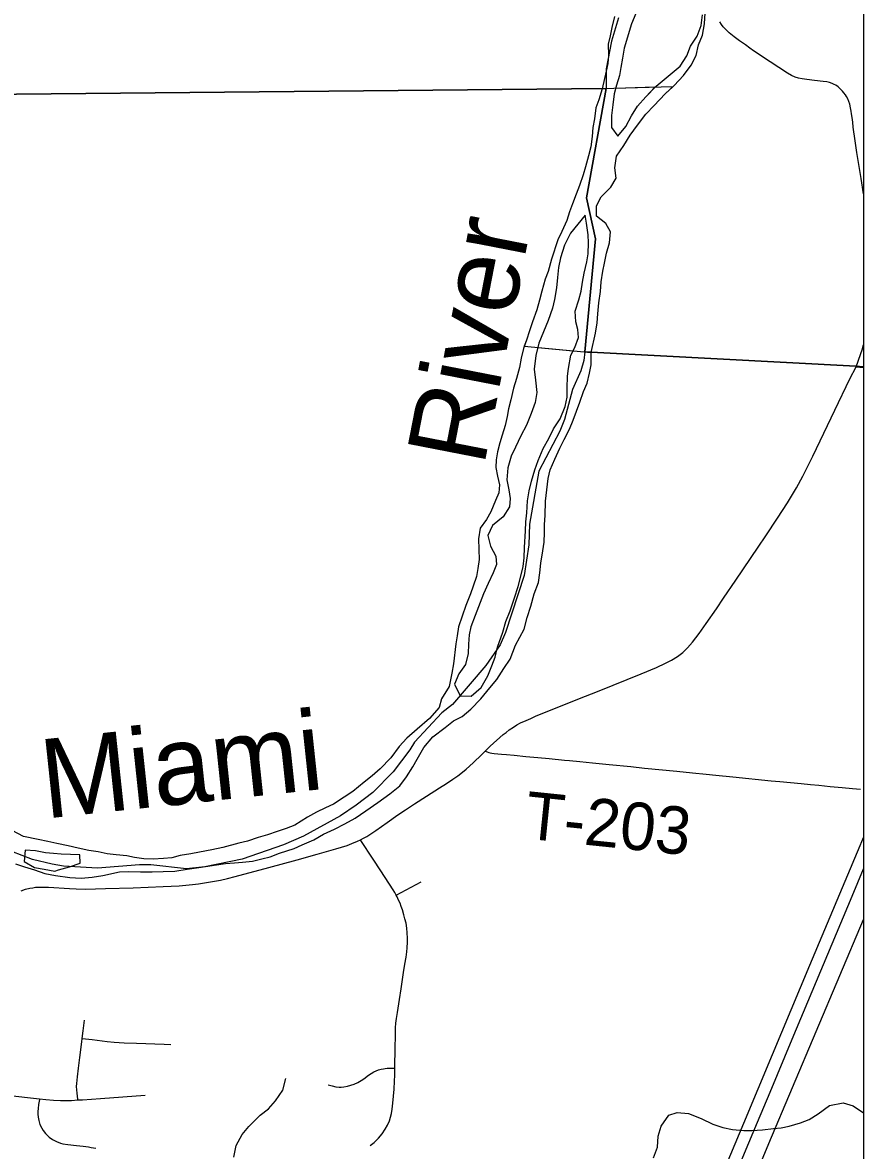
# Model space of a CAD drawing. Extents: x -87 to 2145, y -2128 to 440.
# Drawn here: x 255.22 to 281.8, y 178.57 to 214.23 of the extents above; entities that cross this region are included whole.
import ezdxf

# ---------------------------------------------------------------- set-up
doc = ezdxf.new("R2010")
doc.units = 0
for name, color, linetype in [('GM_X_County_Road', 7, 'Continuous'), ('GM_X_Interstate_Route', 7, 'Continuous'), ('GM_X_Major_River', 7, 'Continuous'), ('GM_X_Major_River_Text', 7, 'Continuous'), ('GM_X_Minor_River', 7, 'Continuous'), ('GM_X_Rail_Line', 7, 'Continuous'), ('GM_X_Township', 7, 'Continuous'), ('GM_X_Township_Road', 7, 'Continuous'), ('GM_X_Township_Road_Text', 7, 'Continuous'), ('GM_X_Township_Text', 7, 'Continuous'), ('SH_Cut_Line', 7, 'Continuous'), ('SH_Text', 7, 'Continuous')]:
    doc.layers.add(name, color=color, linetype=linetype)

msp = doc.modelspace()

# ---------------------------------------------------------------- linework, layer by layer
at = {"layer": 'GM_X_County_Road'}
msp.add_line((281.567, 203.349), (281.801, 203.326), dxfattribs=at)
at = {"layer": 'GM_X_Interstate_Route'}
for points in [[(278.018, 179.429), (278.929, 181.6), (280.107, 184.432), (281.696, 188.213), (281.801, 188.464)], [(278.453, 179.463), (278.849, 180.409), (279.553, 182.088), (281.44, 186.615), (281.801, 187.473)], [(265.644, 155.016), (265.806, 155.447), (265.948, 155.792), (266.105, 156.136), (266.281, 156.489), (266.476, 156.851), (266.665, 157.178), (267.768, 158.911), (268.709, 160.389), (270.982, 163.9), (271.858, 165.306), (272.07, 165.657), (272.693, 166.735), (273.419, 168.076), (274.226, 169.653), (274.883, 171.028), (275.672, 172.831), (276.978, 175.947), (278.453, 179.463)], [(268.918, 161.401), (269.569, 162.413), (270.91, 164.496), (271.65, 165.698), (272.583, 167.319), (273.388, 168.824), (274.151, 170.369), (274.821, 171.832), (275.854, 174.245), (277.608, 178.454), (278.018, 179.429)]]:
    msp.add_lwpolyline(points, dxfattribs=at)
at = {"layer": 'GM_X_Major_River'}
for p, q in [((275.773, 212.196), (273.543, 212.136)), ((275.21, 212.181), (273.967, 212.148)), ((271.077, 203.996), (273.198, 203.799)), ((271.507, 203.956), (272.621, 203.853))]:
    msp.add_line(p, q, dxfattribs=at)
for points in [[(273.198, 203.799), (273.327, 204.406), (273.389, 204.735), (273.409, 205.025), (273.441, 205.365), (273.494, 205.725), (273.515, 206.035), (273.567, 206.365), (273.616, 206.624), (273.678, 206.933), (273.769, 207.262), (273.802, 207.612), (273.661, 207.878), (273.358, 208.109), (273.359, 208.431), (273.51, 208.717), (273.812, 209.028), (273.983, 209.313), (273.944, 209.636), (273.997, 210.005), (274.23, 210.339), (274.432, 210.673), (274.654, 210.987), (274.917, 211.33), (275.188, 211.611), (275.532, 211.971), (275.822, 212.242), (276.114, 212.554), (276.357, 212.877), (276.508, 213.183), (276.59, 213.521), (276.711, 213.829), (276.774, 214.188), (276.797, 214.539)], [(273.933, 214.418), (273.85, 214.069), (273.791, 213.81), (273.731, 213.541), (273.739, 213.189), (273.72, 212.938), (273.671, 212.689), (273.543, 212.136)], [(274.609, 214.515), (274.467, 214.188), (274.238, 213.413)], [(275.25, 212.222), (276.004, 212.849), (276.217, 213.173), (276.338, 213.48), (276.55, 213.794), (276.672, 214.131), (276.714, 214.472)], [(274.238, 213.413), (274.187, 213.103), (274.137, 212.803), (274.088, 212.554), (273.996, 212.246), (273.917, 211.977), (273.874, 211.627), (273.842, 211.287), (273.839, 210.915), (274.04, 210.637), (274.291, 210.939), (274.474, 211.275), (274.655, 211.58), (274.917, 211.882), (275.25, 212.222)], [(273.198, 203.799), (273.327, 204.406), (273.389, 204.735), (273.409, 205.025), (273.441, 205.365), (273.494, 205.725), (273.515, 206.035), (273.567, 206.365), (273.616, 206.624), (273.678, 206.933), (273.769, 207.262), (273.802, 207.612), (273.661, 207.878), (273.358, 208.109), (273.359, 208.431), (273.51, 208.717), (273.812, 209.028), (273.983, 209.313), (273.944, 209.636), (273.997, 210.005), (274.23, 210.339), (274.432, 210.673), (274.654, 210.987), (274.917, 211.33), (275.188, 211.611), (275.532, 211.971), (275.773, 212.196)], [(273.967, 212.148), (273.917, 211.977), (273.874, 211.627), (273.842, 211.287), (273.839, 210.915), (274.04, 210.637), (274.291, 210.939), (274.474, 211.275), (274.655, 211.58), (274.917, 211.882), (275.21, 212.181)], [(273.543, 212.136), (273.44, 211.788), (273.343, 211.528), (273.299, 211.187), (273.246, 210.907), (273.223, 210.626), (273.179, 210.295), (273.106, 210.014), (273.012, 209.664), (272.939, 209.414), (272.824, 209.073), (272.721, 208.803), (272.607, 208.493), (272.514, 208.243)], [(273.543, 212.136), (273.44, 211.788), (273.343, 211.528), (273.299, 211.187), (273.246, 210.907), (273.223, 210.626), (273.179, 210.295), (273.106, 210.014), (273.012, 209.664), (272.939, 209.414), (272.824, 209.073), (272.721, 208.803), (272.607, 208.493), (272.514, 208.243)], [(272.514, 208.243), (272.421, 207.973), (272.267, 207.623), (272.143, 207.363), (271.936, 206.743), (271.831, 206.363), (271.738, 206.113), (271.634, 205.732), (271.56, 205.452), (271.477, 205.142), (271.342, 204.762), (271.248, 204.482), (271.145, 204.192), (271.052, 203.921), (270.978, 203.621), (270.934, 203.32), (270.83, 202.98), (270.737, 202.67), (270.652, 202.3), (270.579, 202.019), (270.536, 201.769), (270.473, 201.489), (270.379, 201.189), (270.306, 200.939), (270.233, 200.658), (270.19, 200.408), (270.177, 200.157), (270.234, 199.886), (270.301, 199.614), (270.278, 199.364), (270.175, 199.114), (270.021, 198.764), (269.888, 198.515), (269.684, 198.246), (269.63, 197.906), (269.646, 197.574), (269.653, 197.253), (269.609, 196.973), (269.566, 196.713), (269.463, 196.413), (269.38, 196.163), (269.235, 195.803), (269.121, 195.464), (268.997, 195.124), (268.954, 194.844), (268.921, 194.583), (268.843, 193.952), (268.79, 193.662), (268.705, 193.242), (268.46, 192.853), (268.386, 192.573), (268.081, 192.226), (267.696, 191.888), (267.372, 191.601), (267.128, 191.343), (266.864, 190.985), (266.529, 190.637), (266.275, 190.419), (266.022, 190.211), (265.658, 189.924), (265.385, 189.736), (265.051, 189.519), (264.799, 189.401), (264.507, 189.264), (264.224, 189.106), (263.83, 188.86), (263.548, 188.752), (263.266, 188.655), (262.964, 188.547), (262.672, 188.46), (262.329, 188.353), (262.058, 188.286), (261.555, 188.151), (261.203, 188.074), (260.811, 187.998), (260.539, 187.95), (260.207, 187.893), (259.936, 187.826), (259.675, 187.799), (259.353, 187.782), (259.053, 187.795), (258.762, 187.828), (258.512, 187.881), (258.181, 187.914), (257.891, 187.947), (257.61, 188.01), (257.32, 188.053), (256.98, 188.127), (256.659, 188.2), (256.309, 188.274), (256.019, 188.337), (255.719, 188.4), (255.248, 188.495), (254.889, 188.69)], [(272.514, 208.243), (272.421, 207.973), (272.267, 207.623), (272.143, 207.363), (271.936, 206.743), (271.831, 206.363), (271.738, 206.113), (271.634, 205.732), (271.56, 205.452), (271.477, 205.142), (271.342, 204.762), (271.248, 204.482), (271.145, 204.192), (271.077, 203.996)], [(273.008, 208.143), (272.542, 207.572), (272.356, 207.194), (272.229, 206.786), (272.165, 206.486), (272.13, 206.167), (272.096, 205.837), (272.03, 205.478), (271.976, 205.199), (271.83, 204.811), (271.539, 204.095), (271.447, 203.698)], [(273.008, 208.143), (272.542, 207.572), (272.356, 207.194), (272.229, 206.786), (272.165, 206.486), (272.13, 206.167), (272.096, 205.837), (272.03, 205.478), (271.976, 205.199), (271.83, 204.811), (271.539, 204.095), (271.507, 203.956)], [(272.549, 203.718), (272.674, 203.952), (272.799, 204.27), (272.772, 204.521), (272.706, 204.772), (272.69, 205.102), (272.806, 205.46), (272.88, 205.739), (272.924, 206.019), (272.978, 206.308), (273.054, 206.667), (273.097, 206.916), (273.112, 207.266), (273.096, 207.517), (273.051, 207.887), (273.008, 208.143)], [(272.621, 203.853), (272.674, 203.952), (272.799, 204.27), (272.772, 204.521), (272.706, 204.772), (272.69, 205.102), (272.806, 205.46), (272.88, 205.739), (272.924, 206.019), (272.978, 206.308), (273.054, 206.667), (273.097, 206.916), (273.112, 207.266), (273.096, 207.517), (273.051, 207.887), (273.008, 208.143)], [(254.998, 187.636), (255.278, 187.543), (255.597, 187.439), (255.927, 187.326), (256.258, 187.262), (256.718, 187.197), (257.069, 187.184), (257.421, 187.21), (257.763, 187.267), (258.285, 187.382), (258.577, 187.389), (258.948, 187.375), (259.319, 187.381), (259.67, 187.388), (260.031, 187.404), (260.423, 187.46), (260.715, 187.508), (261.077, 187.564), (261.348, 187.601), (261.639, 187.639), (261.92, 187.666), (262.171, 187.683), (262.493, 187.72), (262.785, 187.788), (263.046, 187.855), (263.338, 187.972), (263.802, 188.118), (264.054, 188.236), (264.427, 188.393), (264.73, 188.57), (265.083, 188.727), (265.405, 188.894), (265.739, 189.081), (266.072, 189.309), (266.446, 189.575), (266.831, 189.842), (267.145, 190.1), (267.358, 190.388), (267.553, 190.697), (267.696, 190.946), (267.901, 191.305), (268.185, 191.643), (268.58, 191.94), (268.843, 192.148), (269.115, 192.286), (269.389, 192.523), (269.704, 192.851), (269.988, 193.199), (270.212, 193.458), (270.437, 193.806), (270.631, 194.105), (270.806, 194.545), (271.073, 195.053), (271.167, 195.423), (271.291, 195.773), (271.396, 196.163), (271.531, 196.523), (271.574, 196.833), (271.608, 197.134), (271.662, 197.524), (271.706, 197.805), (271.719, 198.105), (271.722, 198.356), (271.745, 198.647), (271.75, 199.098), (271.794, 199.459), (271.838, 199.809), (271.902, 200.09), (272.046, 200.429), (272.2, 200.769), (272.344, 201.048), (272.508, 201.378), (272.621, 201.658), (272.735, 201.947), (272.839, 202.227), (272.953, 202.567), (273.066, 202.827), (273.14, 203.148), (273.193, 203.408), (273.198, 203.799)], [(271.447, 203.698), (271.391, 203.269), (271.436, 202.928), (271.481, 202.538), (271.426, 202.219), (271.301, 201.87), (271.155, 201.502), (270.97, 201.165), (270.804, 200.807), (270.67, 200.519), (270.564, 200.151), (270.529, 199.771), (270.594, 199.451), (270.63, 199.18), (270.617, 198.921), (270.412, 198.604), (270.077, 198.328), (269.932, 198.01), (270.017, 197.679), (270.183, 197.357), (270.199, 197.097), (270.095, 196.829), (269.94, 196.491), (269.795, 196.163), (269.525, 195.488), (269.389, 195.13), (269.335, 194.871), (269.321, 194.581), (269.307, 194.282), (269.222, 193.933), (269.007, 193.636), (268.872, 193.308), (269.057, 192.946), (269.398, 192.932), (269.713, 193.208), (269.928, 193.575), (270.053, 193.893), (270.157, 194.161), (270.232, 194.48), (270.4, 194.957), (270.495, 195.296), (270.63, 195.633), (270.776, 196.041), (270.882, 196.399), (270.976, 196.728), (271.041, 197.027), (271.075, 197.306), (271.09, 197.636), (271.117, 198.155), (271.131, 198.445), (271.156, 198.734), (271.181, 199.113), (271.236, 199.422), (271.31, 199.731), (271.416, 200.09), (271.52, 200.378), (271.676, 200.766), (271.851, 201.074), (272.006, 201.382), (272.211, 201.699), (272.377, 202.087), (272.431, 202.386), (272.435, 202.666), (272.451, 203.045), (272.474, 203.295), (272.549, 203.718)], [(256.445, 187.939), (256.195, 187.962), (255.944, 187.976), (255.634, 188.04), (255.303, 188.064), (255.268, 187.705), (255.597, 187.521), (255.907, 187.467), (256.237, 187.403)], [(256.237, 187.403), (256.358, 187.441), (256.7, 187.536), (257.043, 187.652), (257.026, 187.912), (256.445, 187.939)]]:
    msp.add_lwpolyline(points, dxfattribs=at)
at = {"layer": 'GM_X_Minor_River'}
for points in [[(261.902, 178.36), (261.977, 178.728), (262.163, 179.075), (262.377, 179.332), (262.733, 179.686), (262.997, 179.883), (263.211, 180.139), (263.447, 180.476), (263.542, 180.844)], [(275.169, 178.335), (275.294, 178.672), (275.309, 179.021), (275.404, 179.339), (275.65, 179.685), (275.912, 179.771), (276.272, 179.737), (276.671, 179.583), (277.039, 179.4), (277.359, 179.297), (277.659, 179.234), (278.019, 179.2), (278.27, 179.207), (278.611, 179.223), (278.953, 179.269), (279.204, 179.286), (279.455, 179.343), (279.808, 179.449), (280.09, 179.555), (280.373, 179.732), (280.728, 179.997), (281.16, 180.072), (281.48, 179.979), (281.801, 179.76)]]:
    msp.add_lwpolyline(points, dxfattribs=at)
at = {"layer": 'GM_X_Rail_Line'}
msp.add_lwpolyline([(263.25, 141.507), (272.05, 162.475), (278.812, 178.796), (281.801, 185.877)], dxfattribs=at)
at = {"layer": 'GM_X_Township'}
for points in [[(274.06, 214.372), (273.842, 213.644), (273.669, 212.761), (273.672, 212.146), (252.829, 211.94), (231.858, 211.465)], [(252.829, 211.94), (273.672, 212.146), (273.049, 208.689), (273.334, 207.386), (272.989, 203.823), (272.962, 203.542), (272.869, 203.216), (272.601, 202.627), (272.35, 201.676), (272.205, 201.307), (271.539, 200.049), (271.249, 198.367), (271.222, 197.715), (271.081, 196.744), (270.489, 194.945), (270.314, 194.555), (269.865, 193.898), (268.808, 192.665), (268.474, 192.408), (267.611, 191.484), (267.467, 191.235), (266.938, 190.539), (266.288, 189.884), (265.764, 189.484), (265.267, 189.152), (264.096, 188.512), (263.471, 188.238), (262.162, 187.78), (260.985, 187.541), (260.402, 187.477), (259.27, 187.598), (258.919, 187.602), (257.593, 187.495), (256.511, 187.556), (256.16, 187.62), (255.53, 187.767), (254.881, 188.024)]]:
    msp.add_lwpolyline(points, dxfattribs=at)
at = {"layer": 'GM_X_Township_Road'}
msp.add_line((267.03, 186.647), (267.819, 187.066), dxfattribs=at)
for points in [[(281.801, 208.815), (281.729, 209.3), (281.595, 210.125), (281.539, 210.49), (281.48, 210.92), (281.461, 211.08), (281.441, 211.23), (281.425, 211.344), (281.412, 211.426), (281.392, 211.536), (281.366, 211.647), (281.336, 211.735), (281.304, 211.817), (281.268, 211.892), (281.229, 211.947), (281.186, 212.006), (281.137, 212.064), (281.088, 212.113), (280.997, 212.195), (280.925, 212.244), (280.873, 212.273), (280.808, 212.302), (280.729, 212.332), (280.641, 212.35), (280.528, 212.369), (280.251, 212.401), (280.008, 212.426), (279.863, 212.446), (279.752, 212.471), (279.644, 212.506), (279.525, 212.559), (279.396, 212.629), (278.852, 212.989), (278.329, 213.337), (278.205, 213.422), (278.071, 213.52), (277.885, 213.653), (277.716, 213.777), (277.559, 213.904), (277.438, 214.015), (277.366, 214.096), (277.311, 214.171), (277.262, 214.256)], [(281.567, 203.349), (281.635, 203.528), (281.72, 203.77), (281.756, 203.885), (281.801, 204.043)], [(269.845, 191.196), (270.004, 191.351), (270.417, 191.719), (270.504, 191.789), (270.601, 191.864), (270.737, 191.954), (270.848, 192.024), (270.964, 192.087), (271.135, 192.167), (271.284, 192.232), (271.438, 192.297), (272.882, 192.876), (273.337, 193.06), (273.886, 193.277), (274.777, 193.634), (275.257, 193.842), (275.547, 193.975), (275.729, 194.07), (275.927, 194.191), (276.097, 194.317), (276.237, 194.46), (276.395, 194.644), (276.605, 194.915), (276.834, 195.234), (277.151, 195.692), (277.381, 196.032), (277.769, 196.601), (278.475, 197.648), (278.715, 198), (279.086, 198.56), (279.396, 199.043), (279.684, 199.519), (279.887, 199.892), (280.198, 200.524), (280.894, 201.973), (281.372, 202.963), (281.567, 203.349)], [(265.904, 188.39), (265.999, 188.441), (266.098, 188.5), (266.384, 188.689), (266.742, 188.941), (267.082, 189.18), (267.32, 189.338), (267.609, 189.528), (267.99, 189.771), (268.398, 190.03), (268.626, 190.177), (268.817, 190.305), (268.976, 190.416), (269.125, 190.528), (269.246, 190.627), (269.465, 190.823), (269.734, 191.087), (269.845, 191.196)], [(269.845, 191.196), (269.902, 191.176), (269.962, 191.154), (269.997, 191.143), (270.05, 191.133), (270.124, 191.12), (270.24, 191.108), (270.362, 191.098), (270.516, 191.085), (270.762, 191.063), (271.126, 191.03), (271.504, 190.996), (271.869, 190.96), (272.355, 190.913), (272.513, 190.896), (272.831, 190.864), (273.232, 190.823), (273.76, 190.772), (274.444, 190.705), (274.881, 190.662), (275.902, 190.559), (276.396, 190.508), (276.828, 190.463), (277.131, 190.433), (277.674, 190.379), (278.886, 190.26), (279.155, 190.234), (279.835, 190.168), (280.127, 190.14), (280.392, 190.115), (280.745, 190.081), (281.132, 190.046), (281.455, 190.017), (281.703, 189.994)], [(255.173, 186.783), (255.31, 186.829), (255.449, 186.86), (255.544, 186.878), (255.632, 186.89), (255.708, 186.894), (255.787, 186.897), (255.914, 186.894), (256.043, 186.89), (256.705, 186.851), (256.913, 186.843), (257.205, 186.836), (257.844, 186.851), (258.712, 186.879), (259.663, 186.914), (260.17, 186.94), (260.593, 186.978), (260.784, 187.001), (261.031, 187.038), (261.481, 187.12), (261.697, 187.168), (261.944, 187.227), (263.004, 187.512), (263.904, 187.764), (264.53, 187.94), (265.12, 188.106), (265.479, 188.216), (265.631, 188.272), (265.81, 188.344), (265.904, 188.39)], [(267.03, 186.647), (266.989, 186.726), (266.933, 186.812), (266.541, 187.413), (266.302, 187.779), (265.915, 188.373), (265.904, 188.39)], [(266.989, 181.171), (266.99, 181.309), (266.994, 181.704), (267.006, 182.316), (267.009, 182.451), (267.021, 182.594), (267.042, 182.743), (267.07, 182.932), (267.133, 183.345), (267.184, 183.68), (267.265, 184.198), (267.307, 184.465), (267.342, 184.677), (267.367, 184.85), (267.379, 184.98), (267.387, 185.152), (267.387, 185.284), (267.379, 185.449), (267.364, 185.597), (267.342, 185.757), (267.309, 185.897), (267.277, 186.016), (267.232, 186.174), (267.192, 186.289), (267.152, 186.391), (267.109, 186.486), (267.057, 186.594), (267.03, 186.647)], [(257.105, 182.114), (257.133, 182.352), (257.174, 182.694)], [(256.972, 180.167), (256.969, 180.198), (256.946, 180.379), (256.934, 180.49), (256.93, 180.595), (256.937, 180.687), (256.961, 180.9), (256.993, 181.177), (257.033, 181.514), (257.092, 182.005), (257.105, 182.114)], [(257.105, 182.114), (257.424, 182.076), (257.891, 182.021), (258.12, 181.997), (258.429, 181.979), (258.827, 181.963), (259.701, 181.929), (259.906, 181.921)], [(264.883, 180.647), (265.012, 180.611), (265.125, 180.585), (265.227, 180.574), (265.29, 180.577), (265.38, 180.586), (265.494, 180.606), (265.598, 180.634), (265.705, 180.672), (265.817, 180.724), (265.927, 180.783), (266.008, 180.841), (266.153, 180.947), (266.236, 181.005), (266.322, 181.054), (266.396, 181.09), (266.472, 181.118), (266.554, 181.142), (266.625, 181.157), (266.683, 181.164), (266.746, 181.169), (266.807, 181.171), (266.87, 181.171), (266.989, 181.171)], [(266.212, 178.723), (266.335, 178.826), (266.472, 178.961), (266.585, 179.096), (266.684, 179.245), (266.754, 179.368), (266.817, 179.505), (266.852, 179.623), (266.879, 179.735), (266.907, 179.882), (266.929, 180.07), (266.949, 180.285), (266.962, 180.512), (266.977, 180.757), (266.987, 180.949), (266.989, 181.171)], [(253.549, 180.463), (254.103, 180.397), (255.003, 180.29), (255.471, 180.231), (255.754, 180.201)], [(255.754, 180.201), (255.751, 180.182), (255.727, 180.026), (255.71, 179.903), (255.704, 179.807), (255.704, 179.723), (255.712, 179.623), (255.73, 179.52), (255.77, 179.395), (255.825, 179.276), (255.869, 179.207), (255.95, 179.108), (256.066, 178.995), (256.162, 178.92), (256.293, 178.851), (256.42, 178.802), (256.493, 178.782), (256.647, 178.756), (256.924, 178.732), (257.138, 178.708), (257.222, 178.696), (257.307, 178.684), (257.388, 178.669), (257.532, 178.643)], [(255.754, 180.201), (255.96, 180.18), (256.198, 180.159), (256.42, 180.148), (256.595, 180.147), (256.77, 180.155), (256.972, 180.167)], [(256.972, 180.167), (257.118, 180.176), (257.681, 180.216), (259.093, 180.321)]]:
    msp.add_lwpolyline(points, dxfattribs=at)
at = {"layer": 'GM_X_Township_Text'}
for points in [[(274.06, 214.372), (273.842, 213.644), (273.669, 212.761), (273.672, 212.146), (273.049, 208.689), (273.334, 207.386), (272.989, 203.823), (281.561, 203.363), (281.801, 203.34)], [(281.801, 203.34), (281.561, 203.363), (272.989, 203.823), (272.962, 203.542), (272.869, 203.216), (272.601, 202.627), (272.35, 201.676), (272.205, 201.307), (271.539, 200.049), (271.249, 198.367), (271.222, 197.715), (271.081, 196.744), (270.489, 194.945), (270.314, 194.555), (269.865, 193.898), (268.808, 192.665), (268.474, 192.408), (267.611, 191.484), (267.467, 191.235), (266.938, 190.539), (266.288, 189.884), (265.764, 189.484), (265.267, 189.152), (264.096, 188.512), (263.471, 188.238), (262.162, 187.78), (260.985, 187.541), (260.402, 187.477), (259.27, 187.598), (258.919, 187.602), (257.593, 187.495), (256.511, 187.556), (256.16, 187.62), (255.53, 187.767), (254.881, 188.024)]]:
    msp.add_lwpolyline(points, dxfattribs=at)
at = {"layer": 'SH_Cut_Line'}
msp.add_lwpolyline([(281.801, 203.34), (281.561, 203.363), (272.989, 203.823), (273.334, 207.386), (273.049, 208.689), (273.672, 212.146), (252.829, 211.94), (231.858, 211.465)], dxfattribs=at)
at = {"layer": 'SH_Text'}
msp.add_lwpolyline([(30, 430), (281.801, 430), (281.801, 10), (30, 10)], close=True, dxfattribs=at)

# ---------------------------------------------------------------- texts
at = {"layer": 'GM_X_Major_River_Text'}
for s, height, rotation, p in [('River', 2.493, 78.9753, (269.802, 200.162)), ('Miami', 2.5001, 6.0741, (255.934, 189.061))]:
    msp.add_text(s, height=height, rotation=rotation, dxfattribs=at).set_placement(p)
at = {"layer": 'GM_X_Township_Road_Text'}
msp.add_text('T-203', height=1.5, rotation=354.1232, dxfattribs=at).set_placement((271.055, 188.437))

doc.saveas('drawing.dxf')
